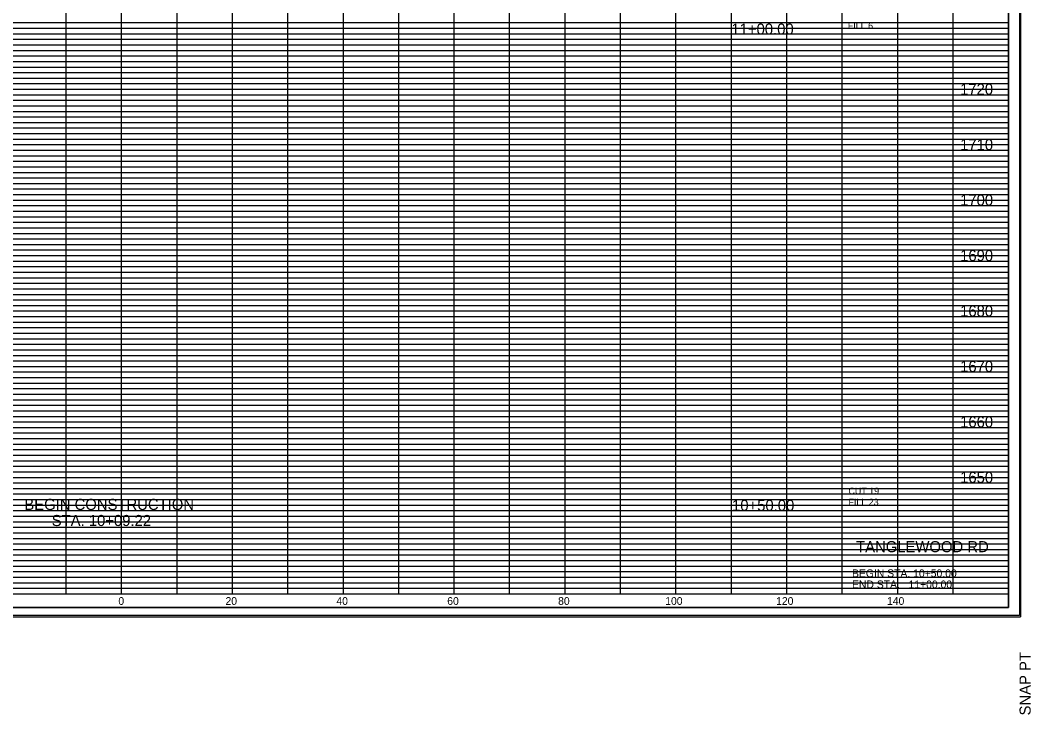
# Model space of a CAD drawing. Extents: x 980 to 1324, y 978 to 1497.
# Drawn here: x 1141.7 to 1324, y 978.2 to 1103.4 of the extents above; entities that cross this region are included whole.
import ezdxf

# ---------------------------------------------------------------- set-up
doc = ezdxf.new("R2010")
doc.units = 0
for name, color, linetype in [('DESIGN - SHEET - Corner Text', 7, 'Continuous'), ('DESIGN - SHEET - Light Grid', 7, 'Continuous'), ('DESIGN - SHEET - Linework', 7, 'Continuous'), ('DESIGN - SHEET - Plot Shape', 7, 'Continuous'), ('DESIGN - TYPICAL - Finished Grade and Subgrade', 7, 'Continuous'), ('DESIGN - TYPICAL - Text', 7, 'Continuous')]:
    doc.layers.add(name, color=color, linetype=linetype)

# ---------------------------------------------------------------- blocks, each defined once
blk = doc.blocks.new('XSTSHT')
at = {"layer": 'DESIGN - SHEET - Light Grid'}
for p, q in [((8, 10.3), (16, 10.3)), ((16, 10.3), (24, 10.3)), ((24, 10.3), (32, 10.3)), ((8, 10.2), (16, 10.2)), ((8, 10.1), (16, 10.1)), ((16, 10.2), (24, 10.2)), ((16, 10.1), (24, 10.1)), ((24, 10.2), (32, 10.2)), ((24, 10.1), (32, 10.1)), ((8, 9.9), (16, 9.9)), ((16, 9.9), (24, 9.9)), ((24, 9.9), (32, 9.9)), ((8, 9.8), (16, 9.8)), ((8, 9.7), (16, 9.7)), ((16, 9.8), (24, 9.8)), ((16, 9.7), (24, 9.7)), ((24, 9.8), (32, 9.8)), ((24, 9.7), (32, 9.7)), ((8, 9.6), (16, 9.6)), ((8, 9.5), (16, 9.5)), ((16, 9.6), (24, 9.6)), ((16, 9.5), (24, 9.5)), ((24, 9.6), (32, 9.6)), ((24, 9.5), (32, 9.5)), ((8, 9.4), (16, 9.4)), ((8, 9.3), (16, 9.3)), ((16, 9.4), (24, 9.4)), ((16, 9.3), (24, 9.3)), ((24, 9.4), (32, 9.4)), ((24, 9.3), (32, 9.3)), ((8, 9.2), (16, 9.2)), ((16, 9.2), (24, 9.2)), ((24, 9.2), (32, 9.2)), ((8, 9.1), (16, 9.1)), ((16, 9.1), (24, 9.1)), ((24, 9.1), (32, 9.1)), ((8, 8.9), (16, 8.9)), ((8, 8.8), (16, 8.8)), ((16, 8.9), (24, 8.9)), ((16, 8.8), (24, 8.8)), ((24, 8.9), (32, 8.9)), ((24, 8.8), (32, 8.8)), ((8, 8.7), (16, 8.7)), ((8, 8.6), (16, 8.6)), ((16, 8.7), (24, 8.7)), ((16, 8.6), (24, 8.6)), ((24, 8.7), (32, 8.7)), ((24, 8.6), (32, 8.6)), ((8, 8.5), (16, 8.5)), ((8, 8.4), (16, 8.4)), ((16, 8.5), (24, 8.5)), ((16, 8.4), (24, 8.4)), ((24, 8.5), (32, 8.5)), ((24, 8.4), (32, 8.4)), ((8, 8.3), (16, 8.3)), ((16, 8.3), (24, 8.3)), ((24, 8.3), (32, 8.3)), ((8, 8.2), (16, 8.2)), ((8, 8.1), (16, 8.1)), ((16, 8.2), (24, 8.2)), ((16, 8.1), (24, 8.1)), ((24, 8.2), (32, 8.2)), ((24, 8.1), (32, 8.1)), ((8, 7.9), (16, 7.9)), ((16, 7.9), (24, 7.9)), ((24, 7.9), (32, 7.9)), ((8, 7.8), (16, 7.8)), ((8, 7.7), (16, 7.7)), ((16, 7.8), (24, 7.8)), ((16, 7.7), (24, 7.7)), ((24, 7.8), (32, 7.8)), ((24, 7.7), (32, 7.7)), ((8, 7.6), (16, 7.6)), ((8, 7.5), (16, 7.5)), ((16, 7.6), (24, 7.6)), ((16, 7.5), (24, 7.5)), ((24, 7.6), (32, 7.6)), ((24, 7.5), (32, 7.5)), ((8, 7.4), (16, 7.4)), ((8, 7.3), (16, 7.3)), ((16, 7.4), (24, 7.4)), ((16, 7.3), (24, 7.3)), ((24, 7.4), (32, 7.4)), ((24, 7.3), (32, 7.3)), ((8, 7.2), (16, 7.2)), ((16, 7.2), (24, 7.2)), ((24, 7.2), (32, 7.2)), ((8, 7.1), (16, 7.1)), ((16, 7.1), (24, 7.1)), ((24, 7.1), (32, 7.1)), ((8, 6.9), (16, 6.9)), ((8, 6.8), (16, 6.8)), ((16, 6.9), (24, 6.9)), ((16, 6.8), (24, 6.8)), ((24, 6.9), (32, 6.9)), ((24, 6.8), (32, 6.8)), ((8, 6.7), (16, 6.7)), ((8, 6.6), (16, 6.6)), ((16, 6.7), (24, 6.7)), ((16, 6.6), (24, 6.6)), ((24, 6.7), (32, 6.7)), ((24, 6.6), (32, 6.6)), ((8, 6.5), (16, 6.5)), ((8, 6.4), (16, 6.4)), ((16, 6.5), (24, 6.5)), ((16, 6.4), (24, 6.4)), ((24, 6.5), (32, 6.5)), ((24, 6.4), (32, 6.4)), ((8, 6.3), (16, 6.3)), ((8, 6.2), (16, 6.2)), ((16, 6.3), (24, 6.3)), ((16, 6.2), (24, 6.2)), ((24, 6.3), (32, 6.3)), ((24, 6.2), (32, 6.2)), ((8, 6.1), (16, 6.1)), ((16, 6.1), (24, 6.1)), ((24, 6.1), (32, 6.1)), ((8, 5.9), (16, 5.9)), ((16, 5.9), (24, 5.9)), ((24, 5.9), (32, 5.9)), ((8, 5.8), (16, 5.8)), ((8, 5.7), (16, 5.7)), ((16, 5.8), (24, 5.8)), ((16, 5.7), (24, 5.7)), ((24, 5.8), (32, 5.8)), ((24, 5.7), (32, 5.7)), ((8, 5.6), (16, 5.6)), ((8, 5.5), (16, 5.5)), ((16, 5.6), (24, 5.6)), ((16, 5.5), (24, 5.5)), ((24, 5.6), (32, 5.6)), ((24, 5.5), (32, 5.5)), ((8, 5.4), (16, 5.4)), ((8, 5.3), (16, 5.3)), ((16, 5.4), (24, 5.4)), ((16, 5.3), (24, 5.3)), ((24, 5.4), (32, 5.4)), ((24, 5.3), (32, 5.3)), ((8, 5.2), (16, 5.2)), ((16, 5.2), (24, 5.2)), ((24, 5.2), (32, 5.2)), ((8, 5.1), (16, 5.1)), ((16, 5.1), (24, 5.1)), ((24, 5.1), (32, 5.1)), ((8, 4.9), (16, 4.9)), ((8, 4.8), (16, 4.8)), ((16, 4.9), (24, 4.9)), ((16, 4.8), (24, 4.8)), ((24, 4.9), (32, 4.9)), ((24, 4.8), (32, 4.8)), ((8, 4.7), (16, 4.7)), ((8, 4.6), (16, 4.6)), ((16, 4.7), (24, 4.7)), ((16, 4.6), (24, 4.6)), ((24, 4.7), (32, 4.7)), ((24, 4.6), (32, 4.6)), ((8, 4.5), (16, 4.5)), ((8, 4.4), (16, 4.4)), ((16, 4.5), (24, 4.5)), ((16, 4.4), (24, 4.4)), ((24, 4.5), (32, 4.5)), ((24, 4.4), (32, 4.4)), ((8, 4.3), (16, 4.3)), ((8, 4.2), (16, 4.2)), ((16, 4.3), (24, 4.3)), ((16, 4.2), (24, 4.2)), ((24, 4.3), (32, 4.3)), ((24, 4.2), (32, 4.2)), ((8, 4.1), (16, 4.1)), ((16, 4.1), (24, 4.1)), ((24, 4.1), (32, 4.1)), ((8, 3.9), (16, 3.9)), ((16, 3.9), (24, 3.9)), ((24, 3.9), (32, 3.9)), ((8, 3.8), (16, 3.8)), ((8, 3.7), (16, 3.7)), ((16, 3.8), (24, 3.8)), ((16, 3.7), (24, 3.7)), ((24, 3.8), (32, 3.8)), ((24, 3.7), (32, 3.7)), ((8, 3.6), (16, 3.6)), ((8, 3.5), (16, 3.5)), ((16, 3.6), (24, 3.6)), ((16, 3.5), (24, 3.5)), ((24, 3.6), (32, 3.6)), ((24, 3.5), (32, 3.5)), ((8, 3.4), (16, 3.4)), ((8, 3.3), (16, 3.3)), ((16, 3.4), (24, 3.4)), ((16, 3.3), (24, 3.3)), ((24, 3.4), (32, 3.4)), ((24, 3.3), (32, 3.3)), ((8, 3.2), (16, 3.2)), ((8, 3.1), (16, 3.1)), ((16, 3.2), (24, 3.2)), ((16, 3.1), (24, 3.1)), ((24, 3.2), (32, 3.2)), ((24, 3.1), (32, 3.1)), ((8, 2.9), (16, 2.9)), ((8, 2.8), (16, 2.8)), ((16, 2.9), (24, 2.9)), ((16, 2.8), (24, 2.8)), ((24, 2.9), (32, 2.9)), ((24, 2.8), (32, 2.8)), ((8, 2.7), (16, 2.7)), ((8, 2.6), (16, 2.6)), ((16, 2.7), (24, 2.7)), ((16, 2.6), (24, 2.6)), ((24, 2.7), (32, 2.7)), ((24, 2.6), (32, 2.6)), ((8, 2.5), (16, 2.5)), ((8, 2.4), (16, 2.4)), ((16, 2.5), (24, 2.5)), ((16, 2.4), (24, 2.4)), ((24, 2.5), (32, 2.5)), ((24, 2.4), (32, 2.4)), ((8, 2.3), (16, 2.3)), ((8, 2.2), (16, 2.2)), ((16, 2.3), (24, 2.3)), ((16, 2.2), (24, 2.2)), ((24, 2.3), (32, 2.3)), ((24, 2.2), (32, 2.2)), ((8, 2.1), (16, 2.1)), ((16, 2.1), (24, 2.1)), ((24, 2.1), (32, 2.1)), ((8, 1.9), (16, 1.9)), ((16, 1.9), (24, 1.9)), ((24, 1.9), (32, 1.9)), ((8, 1.8), (16, 1.8)), ((8, 1.7), (16, 1.7)), ((16, 1.8), (24, 1.8)), ((16, 1.7), (24, 1.7)), ((24, 1.8), (32, 1.8)), ((24, 1.7), (32, 1.7)), ((8, 1.6), (16, 1.6)), ((8, 1.5), (16, 1.5)), ((16, 1.6), (24, 1.6)), ((16, 1.5), (24, 1.5)), ((24, 1.6), (32, 1.6)), ((24, 1.5), (32, 1.5)), ((8, 1.4), (16, 1.4)), ((8, 1.3), (16, 1.3)), ((16, 1.4), (24, 1.4)), ((16, 1.3), (24, 1.3)), ((24, 1.4), (32, 1.4)), ((24, 1.3), (32, 1.3)), ((8, 1.2), (16, 1.2)), ((8, 1.1), (16, 1.1)), ((16, 1.2), (24, 1.2)), ((16, 1.1), (24, 1.1)), ((24, 1.2), (32, 1.2)), ((24, 1.1), (32, 1.1)), ((8, 0.9), (16, 0.9)), ((8, 0.8), (16, 0.8)), ((16, 0.9), (24, 0.9)), ((16, 0.8), (24, 0.8)), ((24, 0.9), (32, 0.9)), ((24, 0.8), (32, 0.8)), ((8, 0.7), (16, 0.7)), ((8, 0.6), (16, 0.6)), ((16, 0.7), (24, 0.7)), ((16, 0.6), (24, 0.6)), ((24, 0.7), (32, 0.7)), ((24, 0.6), (32, 0.6)), ((8, 0.5), (16, 0.5)), ((8, 0.4), (16, 0.4)), ((16, 0.5), (24, 0.5)), ((16, 0.4), (24, 0.4)), ((24, 0.5), (32, 0.5)), ((24, 0.4), (32, 0.4)), ((8, 0.3), (16, 0.3)), ((8, 0.2), (16, 0.2)), ((16, 0.3), (24, 0.3)), ((16, 0.2), (24, 0.2)), ((24, 0.3), (32, 0.3)), ((24, 0.2), (32, 0.2)), ((8, 0.1), (16, 0.1)), ((16, 0.1), (24, 0.1)), ((24, 0.1), (32, 0.1))]:
    blk.add_line(p, q, dxfattribs=at)
at = {"layer": 'DESIGN - SHEET - Linework'}
for p, q in [((32.217, 21.414), (32.217, -0.414)), ((15, 0), (15, 21)), ((16, 0), (16, 21)), ((17, 0), (17, 21)), ((18, 0), (18, 21)), ((19, 0), (19, 21)), ((20, 0), (20, 21)), ((21, 0), (21, 21)), ((22, 0), (22, 21)), ((23, 0), (23, 21)), ((24, 0), (24, 21)), ((25, 0), (25, 21)), ((26, 0), (26, 21)), ((27, 0), (27, 21)), ((28, 0), (28, 20)), ((29, 0), (29, 20)), ((30, 0), (30, 20)), ((31, 0), (31, 20)), ((0, 10), (32, 10)), ((0, 9), (32, 9)), ((0, 8), (32, 8)), ((0, 7), (32, 7)), ((0, 6), (32, 6)), ((0, 5), (32, 5)), ((0, 4), (32, 4)), ((0, 3), (32, 3)), ((0, 2), (32, 2)), ((0, 1), (32, 1)), ((-1.823, -0.414), (32.217, -0.414))]:
    blk.add_line(p, q, dxfattribs=at)
blk.add_lwpolyline([(0, 21), (0, 0), (32, 0), (32, 21), (0, 21)], dxfattribs=at)
at = {"layer": 'DESIGN - SHEET - Plot Shape'}
for points in [[(-1.803, 21.394), (32.197, 21.394), (32.197, -0.394), (-1.803, -0.394)], [(-0.85, 21), (32, 21), (32, -0.25), (-0.85, -0.25)]]:
    blk.add_lwpolyline(points, close=True, dxfattribs=at)
at = {"layer": 'DESIGN - SHEET - Corner Text'}
blk.add_text('SNAP PT  ', height=0.2, rotation=90, dxfattribs=at).set_placement((32.397, -2.194))

msp = doc.modelspace()

# ---------------------------------------------------------------- linework, layer by layer
at = {"layer": 'DESIGN - SHEET - Plot Shape'}
msp.add_lwpolyline([(991.5, 997.5), (1320, 997.5), (1320, 1210), (991.5, 1210)], close=True, dxfattribs=at)

# ---------------------------------------------------------------- block references
at = {"layer": 'DESIGN - TYPICAL - Finished Grade and Subgrade', "xscale": 10, "yscale": 10}
msp.add_blockref('XSTSHT', (1000, 1000), dxfattribs=at)

# ---------------------------------------------------------------- texts
at = {"layer": 'DESIGN - SHEET - Corner Text'}
for s, height, p in [('11+00.00', 2, (1270, 1100.84)), ('1720', 2, (1311.25, 1090)), ('1710', 2, (1311.25, 1080)), ('1700', 2, (1311.25, 1070)), ('1690', 2, (1311.25, 1060)), ('1680', 2, (1311.25, 1050)), ('1670', 2, (1311.25, 1040)), ('1660', 2, (1311.25, 1030)), ('1650', 2, (1311.25, 1020)), ('10+50.00', 2, (1270.11, 1014.95)), ('TANGLEWOOD RD', 2, (1292.49, 1007.5)), ('BEGIN STA. 10+50.00', 1.4, (1291.75, 1003)), ('END STA.   11+00.00', 1.4, (1291.75, 1001)), ('0', 1.4, (1159.42, 998)), ('0', 1.4, (1159.42, 998)), ('20', 1.4, (1178.74, 998)), ('40', 1.4, (1198.74, 998)), ('60', 1.4, (1218.74, 998)), ('80', 1.4, (1238.74, 998)), ('100', 1.4, (1258.06, 998)), ('120', 1.4, (1278.06, 998)), ('140', 1.4, (1298.06, 998))]:
    msp.add_text(s, height=height, dxfattribs=at).set_placement(p)
at = {"layer": 'DESIGN - TYPICAL - Text'}
for s, height, p in [('FILL 6', 1.2, (1291, 1101.84)), ('CUT 19', 1.2, (1291.11, 1017.95)), ('BEGIN CONSTRUCTION', 2, (1142.46, 1015.12)), ('FILL 23', 1.2, (1291.11, 1015.95)), ('STA. 10+09.22', 2, (1147.4, 1012.22))]:
    msp.add_text(s, height=height, dxfattribs=at).set_placement(p)

doc.saveas('drawing.dxf')
